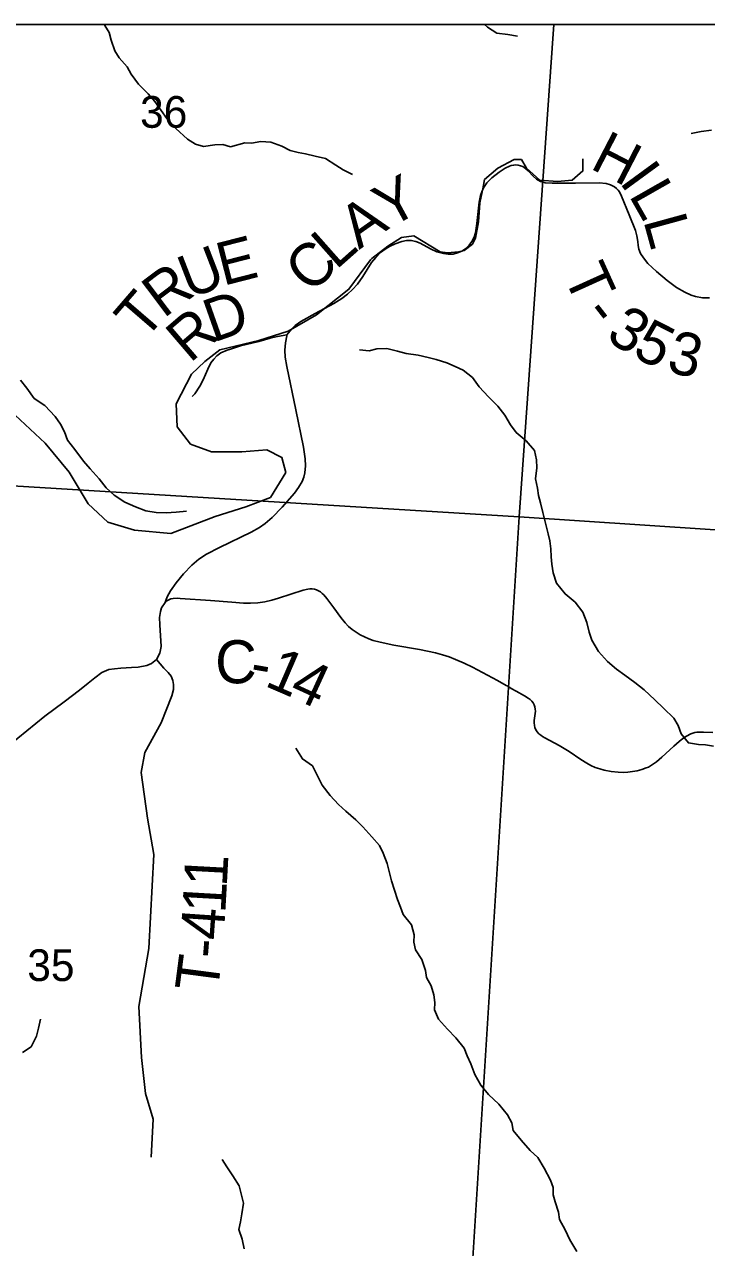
# Model space of a CAD drawing. Extents: x 39.8 to 73.8, y 13 to 35.
# Drawn here: x 43.927 to 44.827, y 32.252 to 33.865 of the extents above; entities that cross this region are included whole.
import ezdxf

# ---------------------------------------------------------------- set-up
doc = ezdxf.new("R2010")
doc.units = 0
for name, color, linetype in [('GM_X_Corporation', 7, 'Continuous'), ('GM_X_County_Road', 7, 'Continuous'), ('GM_X_County_Road_Text', 7, 'Continuous'), ('GM_X_Minor_River', 7, 'Continuous'), ('GM_X_Rail_Line', 7, 'Continuous'), ('GM_X_Section_Text', 7, 'Continuous'), ('GM_X_Township_Road', 7, 'Continuous'), ('GM_X_Township_Road_Text', 7, 'Continuous'), ('SH_Data', 7, 'Continuous')]:
    doc.layers.add(name, color=color, linetype=linetype)

msp = doc.modelspace()

# ---------------------------------------------------------------- linework, layer by layer
at = {"layer": 'GM_X_Corporation'}
msp.add_lwpolyline([(48.663, 33.865), (43.6158, 33.865), (43.5817, 33.4098), (43.5681, 33.1854), (43.5465, 32.861), (43.546, 32.8532), (43.5449, 32.8368), (43.542, 32.7932), (43.5417, 32.788), (43.5004, 32.1696), (43.4879, 31.9992), (43.4604, 31.6234), (43.4594, 31.6102), (43.4278, 31.1804), (43.4119, 30.9413), (43.3611, 30.1764), (43.3611, 30.1536), (43.3561, 30.0855), (43.3525, 30.036), (43.3481, 29.9766)], dxfattribs=at)
for points in [[(44.6253, 33.865), (43.6132, 33.865), (43.573, 33.2772), (44.5795, 33.2157)], [(45.6327, 33.865), (44.6253, 33.865), (44.5795, 33.2157), (45.5809, 33.1493)], [(43.573, 33.2772), (44.5795, 33.2157), (44.516, 32.1957), (43.5036, 32.2603), (43.567, 33.1836)], [(45.5809, 33.1493), (45.5069, 32.1262), (44.516, 32.1957), (44.5795, 33.2157)]]:
    msp.add_lwpolyline(points, close=True, dxfattribs=at)
at = {"layer": 'GM_X_County_Road'}
msp.add_lwpolyline([(43.9062, 32.9141), (43.954, 32.9525), (43.9792, 32.9717), (43.9996, 32.987), (44.0111, 32.9961), (44.0196, 33.0033), (44.0289, 33.0104), (44.0382, 33.0142), (44.0456, 33.0153), (44.0543, 33.0159), (44.0682, 33.0167), (44.0771, 33.0175), (44.0882, 33.0195), (44.0945, 33.0223), (44.1011, 33.0274), (44.1056, 33.0358), (44.1072, 33.0447), (44.1054, 33.073), (44.1052, 33.0827), (44.1066, 33.0905), (44.1076, 33.0956), (44.1124, 33.1026), (44.1136, 33.1037), (44.1149, 33.1048), (44.1174, 33.1062), (44.1202, 33.1072), (44.1231, 33.1078), (44.1292, 33.1082), (44.1324, 33.108), (44.1726, 33.1051), (44.2004, 33.1029), (44.2159, 33.1017), (44.2253, 33.1016), (44.2346, 33.1023), (44.2439, 33.1036), (44.2531, 33.1057), (44.2621, 33.1082), (44.2946, 33.1188), (44.3006, 33.1201), (44.3035, 33.1204), (44.3064, 33.1205), (44.3094, 33.12), (44.3122, 33.1193), (44.3148, 33.1181), (44.3174, 33.1165), (44.3197, 33.1146), (44.322, 33.1125), (44.326, 33.1079), (44.3351, 33.0954), (44.3443, 33.0828), (44.3502, 33.0756), (44.3546, 33.0711), (44.3594, 33.067), (44.3645, 33.0633), (44.3698, 33.06), (44.3754, 33.0571), (44.3812, 33.0546), (44.3871, 33.0526), (44.3962, 33.0502), (44.4144, 33.0464), (44.448, 33.0404), (44.4692, 33.036), (44.4782, 33.0337), (44.487, 33.0309), (44.4957, 33.0276), (44.507, 33.0227), (44.5181, 33.0172), (44.5508, 32.9995), (44.5622, 32.9933), (44.5644, 32.9921), (44.5692, 32.9892), (44.5754, 32.9857), (44.5865, 32.9796), (44.5916, 32.9763), (44.594, 32.9745), (44.5961, 32.9724), (44.5979, 32.9701), (44.5993, 32.9676), (44.6003, 32.9649), (44.6008, 32.962), (44.6009, 32.9591), (44.6007, 32.9561), (44.5994, 32.9469), (44.5993, 32.9437), (44.5996, 32.9405), (44.6003, 32.9375), (44.6017, 32.9345), (44.6034, 32.9319), (44.6055, 32.9295), (44.608, 32.9274), (44.6105, 32.9257), (44.6133, 32.9241), (44.6323, 32.9138), (44.6455, 32.9059), (44.6609, 32.8957), (44.6687, 32.8907), (44.6742, 32.8877), (44.6799, 32.8851), (44.6858, 32.883), (44.6918, 32.8814), (44.701, 32.8797), (44.7103, 32.8787), (44.7166, 32.8785), (44.7228, 32.8787), (44.729, 32.8795), (44.7352, 32.8806), (44.7412, 32.8822), (44.7471, 32.8843), (44.75, 32.8856), (44.7554, 32.8888), (44.7606, 32.8924), (44.7677, 32.8984), (44.7834, 32.9133), (44.7904, 32.9193), (44.7953, 32.923), (44.8004, 32.9263), (44.8058, 32.9292), (44.8086, 32.9303), (44.8114, 32.931), (44.814, 32.9315), (44.8167, 32.9317), (44.8227, 32.9317), (44.8351, 32.931)], dxfattribs=at)
at = {"layer": 'GM_X_Minor_River'}
for p, q in [((44.0317, 33.865), (44.0328, 33.8637)), ((44.0328, 33.8637), (44.0385, 33.8542)), ((44.5337, 33.865), (44.5378, 33.8614)), ((44.5378, 33.8614), (44.5503, 33.8534)), ((44.0385, 33.8542), (44.0415, 33.8444)), ((44.0415, 33.8444), (44.0461, 33.8304)), ((44.5503, 33.8534), (44.5644, 33.8516)), ((44.5644, 33.8516), (44.5772, 33.8497)), ((44.0461, 33.8304), (44.0521, 33.8209)), ((44.0521, 33.8209), (44.0623, 33.8091)), ((44.0623, 33.8091), (44.0676, 33.7993)), ((44.0676, 33.7993), (44.0775, 33.7864)), ((44.0775, 33.7864), (44.09, 33.7735)), ((44.09, 33.7735), (44.099, 33.7633)), ((44.099, 33.7633), (44.1074, 33.7515)), ((44.1074, 33.7515), (44.1146, 33.7409)), ((44.1146, 33.7409), (44.1267, 33.7277)), ((44.1267, 33.7277), (44.1422, 33.7136)), ((44.8197, 33.7238), (44.8065, 33.7211)), ((44.8334, 33.7254), (44.8197, 33.7238)), ((44.1422, 33.7136), (44.1524, 33.7072)), ((44.1524, 33.7072), (44.163, 33.7042)), ((44.163, 33.7042), (44.1782, 33.7061)), ((44.1782, 33.7061), (44.1888, 33.7068)), ((44.1888, 33.7068), (44.1986, 33.7034)), ((44.1986, 33.7034), (44.2178, 33.709)), ((44.2178, 33.709), (44.2265, 33.7086)), ((44.2265, 33.7086), (44.2386, 33.7106)), ((44.2386, 33.7106), (44.2518, 33.7099)), ((44.2518, 33.7099), (44.2666, 33.7046)), ((44.2666, 33.7046), (44.2776, 33.6986)), ((44.2776, 33.6986), (44.2879, 33.6959)), ((44.2879, 33.6959), (44.2977, 33.6945)), ((44.2977, 33.6945), (44.3106, 33.6911)), ((44.3106, 33.6911), (44.3242, 33.6881)), ((44.3242, 33.6881), (44.3375, 33.6794)), ((44.3375, 33.6794), (44.3474, 33.6734)), ((44.3474, 33.6734), (44.3595, 33.6673)), ((43.9218, 33.396), (43.9301, 33.3854)), ((43.9301, 33.3854), (43.9396, 33.3718)), ((43.9396, 33.3718), (43.9539, 33.3623)), ((43.9539, 33.3623), (43.9676, 33.3479)), ((43.9676, 33.3479), (43.9744, 33.3376)), ((43.9744, 33.3376), (43.9797, 33.3278)), ((43.9797, 33.3278), (43.9838, 33.3168)), ((43.9838, 33.3168), (43.9933, 33.3043)), ((43.9933, 33.3043), (44.0047, 33.2891)), ((44.0047, 33.2891), (44.0137, 33.2789)), ((44.0137, 33.2789), (44.0255, 33.2656)), ((44.0255, 33.2656), (44.0349, 33.2539)), ((44.0349, 33.2539), (44.0452, 33.244)), ((44.0452, 33.244), (44.0595, 33.235)), ((44.0595, 33.235), (44.0735, 33.2289)), ((44.0735, 33.2289), (44.0872, 33.2236)), ((44.0872, 33.2236), (44.1008, 33.2213)), ((44.1008, 33.2213), (44.1141, 33.2209)), ((44.1141, 33.2209), (44.1273, 33.2217)), ((44.1273, 33.2217), (44.1409, 33.2232)), ((43.9428, 32.5304), (43.9454, 32.541)), ((43.9454, 32.541), (43.9481, 32.5531)), ((43.9356, 32.5167), (43.9428, 32.5304)), ((43.9246, 32.5092), (43.9356, 32.5167)), ((44.1941, 32.3584), (44.1877, 32.3678)), ((44.2017, 32.3462), (44.1941, 32.3584)), ((44.21, 32.3333), (44.2017, 32.3462)), ((44.213, 32.3227), (44.21, 32.3333)), ((44.2157, 32.3102), (44.213, 32.3227)), ((44.2119, 32.2856), (44.2138, 32.2962)), ((44.2138, 32.2962), (44.2157, 32.3102)), ((44.2096, 32.2757), (44.2119, 32.2856)), ((44.2141, 32.2629), (44.2096, 32.2757)), ((44.2168, 32.2503), (44.2141, 32.2629))]:
    msp.add_line(p, q, dxfattribs=at)
for points in [[(44.4594, 33.4256), (44.4461, 33.4286), (44.4306, 33.4309), (44.4192, 33.4342), (44.4048, 33.4376), (44.3916, 33.4372), (44.3818, 33.4345), (44.3689, 33.436)], [(44.8357, 32.9132), (44.8255, 32.9147), (44.816, 32.9154), (44.8028, 32.9173), (44.7932, 32.9294), (44.7894, 32.9403), (44.7837, 32.9502), (44.77, 32.9634), (44.7586, 32.9744), (44.7445, 32.9872), (44.732, 32.9971), (44.7191, 33.0069), (44.7081, 33.0148), (44.6959, 33.0246), (44.6841, 33.0379), (44.6753, 33.053), (44.6719, 33.0633), (44.6688, 33.0762), (44.6634, 33.0898), (44.6532, 33.103), (44.6402, 33.114), (44.6288, 33.128), (44.6242, 33.1416), (44.6226, 33.153), (44.6218, 33.1629), (44.6214, 33.1735), (44.6199, 33.1837), (44.6179, 33.1932), (44.6141, 33.2072), (44.6106, 33.2213), (44.6075, 33.2341), (44.6052, 33.2436), (44.6037, 33.2535), (44.6013, 33.2656), (44.6028, 33.28), (44.6024, 33.2907), (44.5997, 33.3032), (44.589, 33.3156), (44.5757, 33.3266), (44.5681, 33.3368), (44.5605, 33.3497), (44.5513, 33.3614), (44.5392, 33.3739), (44.5266, 33.3871), (44.5182, 33.3993), (44.5057, 33.4091), (44.4951, 33.414), (44.4841, 33.4185), (44.47, 33.423), (44.4594, 33.4256)], [(44.3507, 32.8274), (44.3412, 32.8361), (44.3301, 32.8482), (44.3195, 32.8615), (44.313, 32.8747), (44.3069, 32.8872), (44.2939, 32.8963), (44.2848, 32.9103)], [(44.6557, 32.2465), (44.6465, 32.262), (44.6401, 32.2753), (44.6328, 32.2889), (44.6316, 32.2984), (44.627, 32.312), (44.6243, 32.3215), (44.6243, 32.331), (44.6208, 32.3408), (44.6124, 32.3567), (44.604, 32.3704), (44.5942, 32.3798), (44.5824, 32.3934), (44.5717, 32.4063), (44.5698, 32.4162), (44.564, 32.4268), (44.5526, 32.4411), (44.5389, 32.4536), (44.529, 32.4661), (44.521, 32.4801), (44.5157, 32.4941), (44.5111, 32.5047), (44.5069, 32.5146), (44.4958, 32.5286), (44.4848, 32.5399), (44.473, 32.5532), (44.468, 32.5653), (44.4684, 32.5752), (44.4672, 32.585), (44.4634, 32.5968), (44.4572, 32.6078), (44.4561, 32.6172), (44.4511, 32.6316), (44.4427, 32.6445), (44.4408, 32.6544), (44.4411, 32.6642), (44.4376, 32.6775), (44.4266, 32.6911), (44.4228, 32.7006), (44.4189, 32.7108), (44.4113, 32.7355), (44.4055, 32.7582), (44.4001, 32.7718), (44.3952, 32.7821), (44.3853, 32.7934), (44.3735, 32.8066), (44.364, 32.8161), (44.3507, 32.8274)]]:
    msp.add_lwpolyline(points, dxfattribs=at)
at = {"layer": 'GM_X_Rail_Line'}
msp.add_lwpolyline([(43.9081, 33.3558), (43.9544, 33.3126), (43.9859, 33.2743), (44.011, 33.2328), (44.0369, 33.2085), (44.072, 33.1978), (44.1199, 33.1937), (44.1787, 33.2161), (44.2189, 33.2287), (44.2515, 33.2412), (44.2716, 33.2739), (44.2666, 33.294), (44.2465, 33.304), (44.2139, 33.3015), (44.1737, 33.3015), (44.1461, 33.3116), (44.1285, 33.3342), (44.1269, 33.3647), (44.1473, 33.4038), (44.1648, 33.4205), (44.1845, 33.4357), (44.236, 33.4482), (44.275, 33.4606), (44.3123, 33.4819), (44.3549, 33.5157), (44.3833, 33.5547), (44.3851, 33.5565), (44.4064, 33.5725), (44.4244, 33.584), (44.4408, 33.5861), (44.4753, 33.5651), (44.4849, 33.5637), (44.4995, 33.5652), (44.5068, 33.5669), (44.5178, 33.5751), (44.5221, 33.583), (44.5261, 33.6048), (44.5278, 33.6295), (44.5318, 33.6482), (44.5336, 33.6604), (44.5513, 33.6753), (44.5731, 33.6869), (44.5825, 33.6869), (44.5892, 33.6755), (44.607, 33.6595), (44.63, 33.6577), (44.6495, 33.6595), (44.6637, 33.6719), (44.6637, 33.6879)], dxfattribs=at)
at = {"layer": 'GM_X_Township_Road'}
for points in [[(44.2729, 33.4545), (44.273, 33.4554), (44.2795, 33.4635), (44.2839, 33.4679), (44.2915, 33.4732), (44.3106, 33.4837), (44.3352, 33.497), (44.3457, 33.5036), (44.3531, 33.5092), (44.3599, 33.5155), (44.3661, 33.5225), (44.3732, 33.5327), (44.3849, 33.551), (44.3904, 33.5577), (44.3967, 33.5642), (44.4028, 33.5686), (44.4085, 33.572), (44.4159, 33.5756), (44.4249, 33.5785), (44.4309, 33.5799), (44.4371, 33.5801), (44.4432, 33.5789), (44.4489, 33.5765), (44.4624, 33.569), (44.471, 33.5653), (44.4799, 33.5627), (44.4861, 33.5619), (44.4923, 33.5621), (44.4983, 33.5636), (44.5039, 33.5661), (44.5091, 33.5696), (44.5136, 33.5739), (44.5173, 33.5789), (44.52, 33.5844), (44.5218, 33.5903), (44.5237, 33.6026), (44.5267, 33.6304), (44.5285, 33.6395), (44.5306, 33.6454), (44.5335, 33.6509), (44.5371, 33.6559), (44.5436, 33.6625), (44.5533, 33.6703), (44.5612, 33.6753), (44.5667, 33.6781), (44.5691, 33.6789), (44.5723, 33.6796), (44.5753, 33.6797), (44.5784, 33.6794), (44.5814, 33.6787), (44.5843, 33.6776), (44.5879, 33.6752), (44.5915, 33.6717), (44.5978, 33.6648), (44.6025, 33.6609), (44.6079, 33.6579), (44.6139, 33.6562), (44.6231, 33.6556), (44.654, 33.6557), (44.6849, 33.656), (44.6941, 33.6552), (44.7, 33.6536), (44.7055, 33.6508), (44.7079, 33.6488), (44.71, 33.6466), (44.7119, 33.6441), (44.7147, 33.6387), (44.7246, 33.6137), (44.7328, 33.5933), (44.7349, 33.5863), (44.736, 33.5789), (44.7366, 33.5735), (44.7376, 33.5686), (44.7397, 33.5629), (44.7436, 33.5571), (44.7494, 33.5499), (44.7605, 33.5392), (44.7747, 33.5273), (44.7873, 33.5182), (44.798, 33.5119), (44.8064, 33.508), (44.8123, 33.5062), (44.8216, 33.5046), (44.8308, 33.5045)], [(44.1124, 33.1026), (44.1129, 33.1037), (44.1135, 33.1052), (44.1153, 33.11), (44.1196, 33.1179), (44.127, 33.1283), (44.1368, 33.1404), (44.1477, 33.1516), (44.157, 33.1599), (44.1672, 33.1664), (44.1843, 33.175), (44.2262, 33.1955), (44.237, 33.2015), (44.2446, 33.2067), (44.2539, 33.2147), (44.2667, 33.2281), (44.283, 33.2469), (44.2886, 33.2543), (44.2931, 33.2622), (44.2953, 33.2679), (44.2968, 33.2738), (44.2976, 33.2829), (44.2973, 33.2921), (44.2952, 33.3074), (44.2849, 33.3568), (44.2731, 33.4138), (44.2709, 33.4261), (44.2703, 33.4355), (44.2711, 33.4449), (44.2729, 33.4545)], [(44.273, 33.4554), (44.2656, 33.4543), (44.2586, 33.453), (44.2511, 33.4512), (44.2361, 33.447), (44.212, 33.441), (44.1988, 33.4369)], [(44.1988, 33.4369), (44.1944, 33.4355), (44.1859, 33.4317), (44.1809, 33.4281), (44.1766, 33.4237), (44.173, 33.4186), (44.1687, 33.4104), (44.1627, 33.3961), (44.1582, 33.388), (44.1515, 33.3777), (44.148, 33.3743)], [(44.1011, 33.0274), (44.1108, 33.0161), (44.1167, 33.0104), (44.1207, 33.0054), (44.1229, 32.9999), (44.1237, 32.9945), (44.1235, 32.9878), (44.1215, 32.9793), (44.1072, 32.9438), (44.0858, 32.9046), (44.0809, 32.8785), (44.0891, 32.8181), (44.0977, 32.7703), (44.091, 32.6463), (44.0779, 32.5697), (44.0812, 32.5025), (44.0868, 32.4551), (44.0966, 32.4213), (44.0942, 32.3712)]]:
    msp.add_lwpolyline(points, dxfattribs=at)
at = {"layer": 'SH_Data'}
msp.add_line((41.863, 33.865), (48.663, 33.865), dxfattribs=at)

# ---------------------------------------------------------------- texts
at = {"layer": 'GM_X_County_Road_Text'}
for s, rotation, p in [('C', 359.8049, (44.1784, 32.9961)), ('1', 336.6388, (44.2422, 32.9933)), ('-', 350.4017, (44.2226, 32.9962)), ('4', 335.3295, (44.274, 32.9795))]:
    msp.add_text(s, height=0.0568, rotation=rotation, dxfattribs=at).set_placement(p)
at = {"layer": 'GM_X_Section_Text'}
for s, p in [('36', (44.0795, 33.7287)), ('35', (43.9307, 32.6033))]:
    msp.add_text(s, height=0.04186, rotation=0, dxfattribs=at).set_placement(p)
at = {"layer": 'GM_X_Township_Road_Text'}
for s, rotation, p in [('H', 332.6302, (44.6715, 33.6759)), ('I', 306.1502, (44.7107, 33.6574)), ('Y', 28.6266, (44.4078, 33.5954)), ('L', 299.6311, (44.7235, 33.6399)), ('A', 35.0588, (44.3684, 33.5675)), ('L', 285.3544, (44.7431, 33.6065)), ('E', 14.3647, (44.189, 33.52)), ('L', 41.491, (44.3378, 33.5404)), ('U', 21.1879, (44.1441, 33.5025)), ('C', 44.7071, (44.3053, 33.5082)), ('T', 294.3585, (44.6373, 33.534)), ('R', 36.9339, (44.1104, 33.4765)), ('T', 49.2462, (44.085, 33.4465)), ('D', 19.4568, (44.1759, 33.4451)), ('-', 307.9152, (44.6624, 33.4828)), ('3', 327.2448, (44.6921, 33.4503)), ('R', 40.5492, (44.1452, 33.4175)), ('5', 333.057, (44.727, 33.4283)), ('3', 347.2075, (44.7725, 33.4072)), ('1', 86.913, (44.1938, 32.7269)), ('1', 86.7646, (44.1918, 32.6918)), ('4', 86.12, (44.1894, 32.6562)), ('-', 85.3485, (44.1874, 32.6321)), ('T', 82.5651, (44.1816, 32.587))]:
    msp.add_text(s, height=0.0568, rotation=rotation, dxfattribs=at).set_placement(p)

doc.saveas('drawing.dxf')
